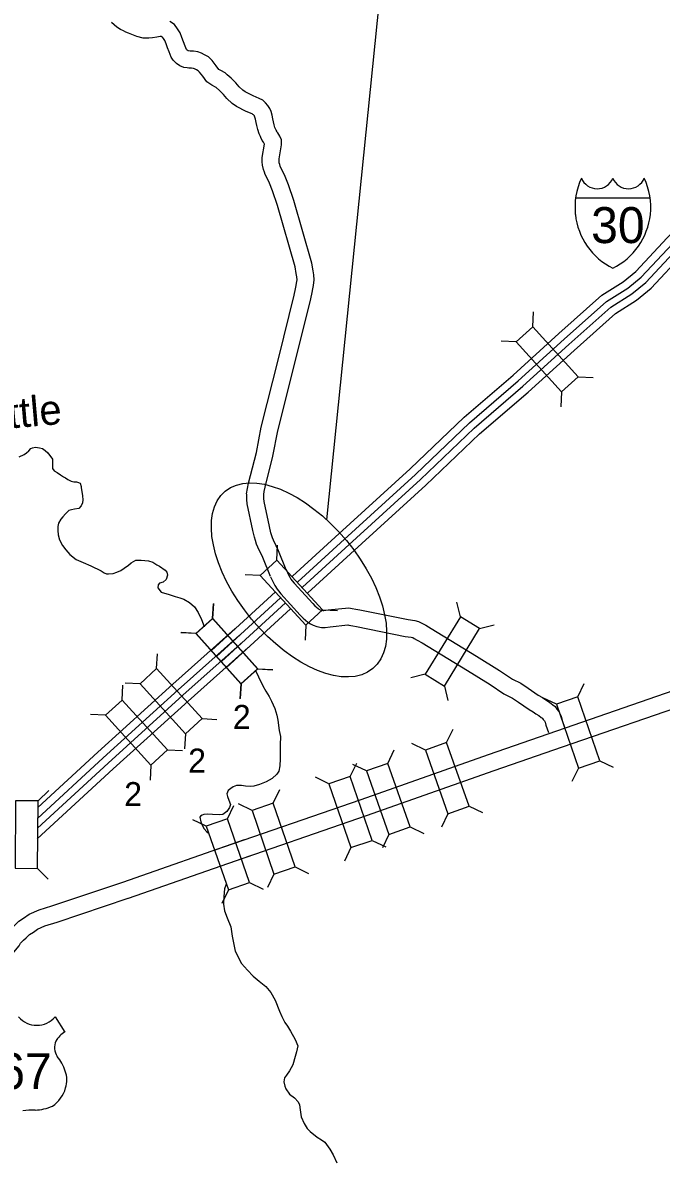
# Model space of a CAD drawing. Extents: x 8749 to 11879, y 13275 to 15339.
# Drawn here: x 9014.9 to 9239.9, y 14666 to 15065.6 of the extents above; entities that cross this region are included whole.
import ezdxf

# ---------------------------------------------------------------- set-up
doc = ezdxf.new("R2010")
doc.units = 0
for name, color, linetype in [('Level 10', 7, 'Continuous'), ('Level 15', 7, 'Continuous'), ('Level 19', 7, 'Continuous'), ('Level 2', 7, 'Continuous'), ('Level 20', 7, 'Continuous'), ('Level 22', 7, 'Continuous'), ('Level 23', 7, 'Continuous'), ('Level 9', 7, 'Continuous'), ('R_Draft', 7, 'Continuous')]:
    doc.layers.add(name, color=color, linetype=linetype)

msp = doc.modelspace()

# ---------------------------------------------------------------- linework, layer by layer
at = {"layer": 'Level 10'}
for points in [[(9093.8, 14899.41), (9093.78, 14899.73), (9094.04, 14901.56), (9094.46, 14903.38), (9097.2, 14914.21), (9098.91, 14923.18), (9105.09, 14947.68), (9110.5, 14969.7), (9110.99, 14971.93), (9111.24, 14973.07), (9111.4, 14973.93), (9111.53, 14975.1), (9111.45, 14976.12), (9111.26, 14977.27), (9110.85, 14979.62), (9104.62, 15001.21), (9102.93, 15006.38), (9101.8, 15009.08), (9101.02, 15010.9), (9100.34, 15012.19), (9100.03, 15012.93), (9099.68, 15013.94), (9099.31, 15015.39), (9099.25, 15016.66), (9099.26, 15018.16), (9100.07, 15022.89), (9099.7, 15023.51), (9099.26, 15024.13), (9098.77, 15025.17), (9098.66, 15025.51), (9098.17, 15026.52), (9097.7, 15028.06), (9097.39, 15029.37), (9097.15, 15030.48), (9096.87, 15031.7), (9096.71, 15032.41), (9096.6, 15032.65), (9096.5, 15032.82), (9096.16, 15033.16), (9095.96, 15033.35), (9095.72, 15033.47), (9093.57, 15034.38), (9090.24, 15036.07), (9088.65, 15037.17), (9086.84, 15038.92), (9085.57, 15040.34), (9084.18, 15041.71), (9083, 15042.79), (9082.84, 15042.92), (9081.57, 15043.57), (9079.76, 15044.81), (9078.29, 15046.83), (9077.19, 15048.23), (9076.7, 15048.7), (9076.14, 15049.02), (9075.4, 15049.38), (9075.09, 15049.5), (9074.39, 15049.59), (9073.45, 15049.67), (9072.79, 15049.71), (9071.71, 15049.83), (9070.29, 15050.45), (9069.06, 15051.25), (9067.88, 15052.4), (9067.17, 15053.5), (9066.45, 15055.36), (9065.95, 15056.83), (9065.41, 15058.2), (9064.97, 15059.32), (9064.47, 15060.1), (9064.14, 15060.57), (9063.93, 15060.7), (9063.76, 15060.77), (9063.67, 15060.79), (9063.34, 15060.78), (9062.17, 15060.57), (9060.58, 15060.34), (9059.36, 15060.22), (9057.38, 15060.14), (9055.14, 15060.82), (9052.16, 15061.95), (9051.26, 15062.29), (9050.36, 15062.72), (9049.33, 15063.25), (9048.09, 15064), (9046.21, 15065.72)], [(9099.81, 14899.41), (9099.8, 14899.45), (9099.95, 14900.46), (9100.29, 14901.97), (9103.06, 14912.92), (9104.77, 14921.89), (9110.91, 14946.23), (9116.34, 14968.34), (9116.85, 14970.64), (9117.13, 14971.9), (9117.34, 14973.05), (9117.56, 14975), (9117.41, 14976.86), (9117.17, 14978.28), (9116.7, 14980.97), (9110.36, 15002.98), (9108.55, 15008.47), (9107.33, 15011.42), (9106.44, 15013.49), (9105.76, 15014.76), (9105.63, 15015.08), (9105.43, 15015.66), (9105.28, 15016.26), (9105.26, 15016.79), (9105.26, 15017.65), (9106.11, 15022.63), (9106.03, 15024.38), (9105.44, 15025.61), (9104.72, 15026.8), (9104.47, 15027.15), (9104.36, 15027.39), (9104.23, 15027.77), (9103.77, 15028.73), (9103.49, 15029.63), (9103.24, 15030.69), (9103.01, 15031.77), (9102.72, 15033.04), (9102.41, 15034.38), (9101.92, 15035.42), (9101.3, 15036.49), (9100.37, 15037.43), (9099.45, 15038.32), (9098.21, 15038.93), (9096.09, 15039.83), (9093.31, 15041.24), (9092.47, 15041.82), (9091.16, 15043.08), (9089.92, 15044.47), (9088.32, 15046.06), (9086.94, 15047.31), (9086.18, 15047.95), (9084.65, 15048.74), (9084, 15049.18), (9083.07, 15050.45), (9081.66, 15052.26), (9080.31, 15053.55), (9078.95, 15054.32), (9077.82, 15054.88), (9076.57, 15055.37), (9075, 15055.56), (9073.89, 15055.65), (9073.32, 15055.69), (9073.28, 15055.69), (9073.14, 15055.75), (9072.82, 15055.96), (9072.56, 15056.21), (9072.55, 15056.24), (9072.08, 15057.42), (9071.59, 15058.88), (9071, 15060.39), (9070.33, 15062.08), (9069.44, 15063.46), (9068.37, 15064.96), (9066.74, 15066.03)], [(9102.19, 14870.6), (9099.47, 14877.22), (9097.77, 14880.85), (9097.24, 14881.99), (9096.87, 14883.22), (9096.53, 14884.46), (9095.93, 14886.79), (9093.99, 14896.19), (9093.88, 14897.7), (9093.8, 14899.41)], [(9107.75, 14872.88), (9104.97, 14879.64), (9103.21, 14883.39), (9102.86, 14884.14), (9102.64, 14884.87), (9102.33, 14885.99), (9101.78, 14888.15), (9099.95, 14897.03), (9099.87, 14898.07), (9099.81, 14899.41)], [(9107.7, 14872.99), (9108.55, 14871.14), (9108.95, 14870.35), (9109.4, 14869.64), (9109.85, 14869.08), (9110.48, 14868.17), (9117.06, 14861.05), (9117.78, 14860.28), (9118.4, 14859.77), (9118.96, 14859.27), (9119.24, 14859.09), (9119.66, 14858.88), (9120.09, 14858.72), (9120.66, 14858.62), (9121.01, 14858.63), (9122.55, 14858.79), (9129.79, 14859.56), (9130.97, 14859.28), (9132.25, 14859.07), (9133.64, 14858.8), (9150.64, 14855.4), (9153.07, 14855.06), (9154.34, 14854.68), (9155.52, 14854.17), (9156.9, 14853.39), (9158.75, 14852.3), (9174.72, 14842.55), (9182.86, 14837.51), (9187.42, 14834.44), (9190.43, 14832.95), (9192.94, 14831.27), (9196.51, 14828.81), (9197.97, 14827.97), (9199.13, 14827.12), (9200.07, 14826.51), (9201.08, 14825.79), (9201.64, 14825.39), (9202.44, 14824.74), (9203.1, 14823.83), (9203.77, 14822.97), (9204.62, 14821.32), (9204.94, 14819.84), (9205.77, 14817.52)], [(9102.24, 14870.48), (9103.15, 14868.53), (9103.74, 14867.36), (9104.52, 14866.14), (9105.03, 14865.5), (9105.8, 14864.4), (9112.66, 14856.97), (9113.66, 14855.89), (9114.51, 14855.2), (9115.32, 14854.49), (9116.28, 14853.86), (9117.25, 14853.39), (9118.46, 14852.91), (9120.21, 14852.61), (9121.41, 14852.64), (9123.19, 14852.83), (9129.41, 14853.48), (9129.79, 14853.39), (9131.18, 14853.16), (9132.48, 14852.91), (9149.63, 14849.48), (9151.79, 14849.18), (9152.28, 14849.03), (9152.85, 14848.78), (9153.91, 14848.19), (9155.66, 14847.16), (9171.58, 14837.43), (9179.61, 14832.47), (9184.4, 14829.24), (9187.42, 14827.75), (9189.57, 14826.3), (9193.3, 14823.74), (9194.68, 14822.94), (9195.72, 14822.18), (9196.69, 14821.55), (9197.6, 14820.9), (9198, 14820.62), (9198.03, 14820.59), (9198.3, 14820.22), (9198.7, 14819.71), (9198.93, 14819.27), (9199.16, 14818.19), (9200.09, 14815.59)]]:
    msp.add_lwpolyline(points, dxfattribs=at)
at = {"layer": 'Level 15'}
for points in [[(9082.3, 14774.19), (9134.08, 14792.01), (9179.01, 14807.86), (9203.08, 14816.22), (9250.19, 14832.47)], [(9084.43, 14768.58), (9136.06, 14786.34), (9180.99, 14802.2), (9205.04, 14810.55), (9252.15, 14826.8)], [(9050.15, 14762.91), (9092.98, 14777.87)], [(9052.12, 14757.24), (9094.96, 14772.2)], [(8907.81, 14602.87), (8921.05, 14621.45), (8947.08, 14657.8), (8972.67, 14693.47), (8988.96, 14716.39), (8999.9, 14731.87), (9003.89, 14737.5), (9007.02, 14741.88), (9008.71, 14743.96), (9009.42, 14745.09), (9010.95, 14746.66), (9011.98, 14747.67), (9013.58, 14749.11), (9015.15, 14750.23), (9017.12, 14751.64), (9020.65, 14753.18), (9025.2, 14754.54), (9050.18, 14762.92)], [(8915.18, 14602.87), (8925.93, 14617.96), (8951.96, 14654.31), (8977.56, 14689.98), (8993.86, 14712.92), (9004.8, 14728.41), (9008.78, 14734.02), (9011.79, 14738.24), (9013.59, 14740.45), (9014.16, 14741.36), (9015.2, 14742.43), (9016.09, 14743.3), (9017.33, 14744.42), (9018.64, 14745.34), (9020.11, 14746.4), (9022.71, 14747.54), (9027.01, 14748.81), (9052.09, 14757.23)]]:
    msp.add_lwpolyline(points, dxfattribs=at)
at = {"layer": 'Level 19'}
for points in [[(9109.92, 14870.66), (9124.94, 14884.43), (9151.41, 14908.53), (9170.43, 14926.73), (9187.67, 14941.52), (9203.82, 14956.17), (9218.94, 14969.62), (9226.41, 14974.36), (9230.86, 14977.96), (9241.9, 14989.81), (9245.61, 14993.6)], [(9111.83, 14868.69), (9126.79, 14882.4), (9153.28, 14906.52), (9172.28, 14924.69), (9189.49, 14939.46), (9205.66, 14954.13), (9220.6, 14967.41), (9228.02, 14972.12), (9232.74, 14975.94), (9243.89, 14987.91), (9247.58, 14991.68)], [(9113.46, 14866.79), (9128.48, 14880.55), (9154.99, 14904.7), (9173.96, 14922.84), (9191.14, 14937.58), (9207.33, 14952.27), (9222.11, 14965.41), (9229.48, 14970.09), (9234.45, 14974.11), (9245.7, 14986.18), (9249.37, 14989.93)], [(9115.34, 14864.79), (9130.33, 14878.52), (9156.86, 14902.69), (9175.8, 14920.8), (9192.96, 14935.52), (9209.17, 14950.22), (9223.77, 14963.21), (9231.09, 14967.85), (9236.33, 14972.09), (9247.69, 14984.28), (9251.33, 14988.01)], [(9081.38, 14844.52), (9103.94, 14865.19)], [(9083.14, 14842.4), (9105.71, 14863.08)], [(9084.89, 14840.6), (9107.42, 14861.26)], [(9086.55, 14838.4), (9109.22, 14859.18)], [(9020.2, 14789.18), (9041.41, 14808.68), (9067.8, 14832.65), (9089.68, 14852.19)], [(9020.04, 14785.3), (9043.26, 14806.65), (9069.64, 14830.6), (9091.24, 14849.9)], [(9020.08, 14781.94), (9044.95, 14804.81), (9071.32, 14828.75), (9092.5, 14847.67)], [(9020.01, 14778.14), (9046.81, 14802.78), (9073.16, 14826.7), (9094.26, 14845.56)]]:
    msp.add_lwpolyline(points, dxfattribs=at)
at = {"layer": 'Level 2'}
for points in [[(9013.68, 14912.68), (9015.4, 14913.49), (9016.25, 14914.11), (9016.99, 14914.87), (9017.79, 14915.64), (9018.35, 14915.92), (9019.39, 14916.06), (9020.82, 14915.92), (9021.84, 14915.59), (9022.83, 14914.91), (9023.79, 14914.13), (9025.43, 14911.91), (9025.44, 14911.13), (9025.42, 14910.11), (9025.4, 14909.31), (9025.36, 14908.65), (9025.94, 14907.81), (9027.05, 14907.25), (9028.21, 14906.34), (9029.31, 14905.66), (9029.95, 14905.28), (9030.79, 14904.7), (9031.99, 14904.12), (9032.89, 14903.85), (9033.89, 14903.93), (9034.55, 14903.71), (9035.09, 14903.39), (9035.45, 14902.25), (9035.54, 14901.85), (9035.66, 14900.53), (9035.98, 14898.95), (9036.09, 14897.55), (9035.91, 14896.47), (9035.45, 14895.45), (9034.64, 14894.53), (9033.16, 14894.24), (9032.08, 14894.04), (9031.14, 14893.82), (9029.97, 14892.69), (9029.05, 14891.61), (9028.31, 14890.79), (9027.54, 14889.3), (9027.28, 14888.22), (9027.28, 14886.74), (9027.35, 14885.28), (9027.89, 14883.46), (9028.96, 14881.44), (9030.04, 14879.98), (9031.51, 14878.27), (9033.73, 14876.53), (9036.17, 14875.44), (9038.91, 14874.32), (9042.47, 14872.61), (9043.6, 14871.83), (9044.38, 14871.49), (9045.14, 14871.46), (9046.75, 14871.6), (9048.03, 14872.06), (9049.41, 14872.73), (9050.63, 14873.49), (9052.12, 14874.58), (9053.12, 14875.38), (9054.74, 14876.27), (9056.61, 14876.27), (9059.25, 14876.06), (9060.69, 14875.62), (9062.16, 14874.62), (9063.04, 14874.15), (9065.02, 14872.79), (9065.64, 14872.09), (9065.92, 14871.01), (9065.39, 14869.55), (9064.35, 14868.6), (9063.11, 14868.2), (9062.6, 14867.68), (9062.5, 14866.56), (9063.62, 14865.08), (9066.46, 14864.21), (9068.62, 14863.53), (9070.3, 14863), (9071.64, 14862.52), (9073.63, 14861.4), (9075.41, 14859.93), (9076.73, 14857.91), (9077.92, 14855.41), (9078.48, 14853.89), (9078.79, 14852.87)], [(9013.68, 14912.68), (9015.4, 14913.49), (9016.25, 14914.11), (9016.99, 14914.87), (9017.79, 14915.64), (9018.35, 14915.92), (9019.39, 14916.06), (9020.82, 14915.92), (9021.84, 14915.59), (9022.83, 14914.91), (9023.79, 14914.13), (9025.43, 14911.91), (9025.44, 14911.13), (9025.42, 14910.11), (9025.4, 14909.31), (9025.36, 14908.65), (9025.94, 14907.81), (9027.05, 14907.25), (9028.21, 14906.34), (9029.31, 14905.66), (9029.95, 14905.28), (9030.79, 14904.7), (9031.99, 14904.12), (9032.89, 14903.85), (9033.89, 14903.93), (9034.55, 14903.71), (9035.09, 14903.39), (9035.45, 14902.25), (9035.54, 14901.85), (9035.66, 14900.53), (9035.98, 14898.95), (9036.09, 14897.55), (9035.91, 14896.47), (9035.45, 14895.45), (9034.64, 14894.53), (9033.16, 14894.24), (9032.08, 14894.04), (9031.14, 14893.82), (9029.97, 14892.69), (9029.05, 14891.61), (9028.31, 14890.79), (9027.54, 14889.3), (9027.28, 14888.22), (9027.28, 14886.74), (9027.35, 14885.28), (9027.89, 14883.46), (9028.96, 14881.44), (9030.04, 14879.98), (9031.51, 14878.27), (9033.73, 14876.53), (9036.17, 14875.44), (9038.91, 14874.32), (9042.47, 14872.61), (9043.6, 14871.83), (9044.38, 14871.49), (9045.14, 14871.46), (9046.75, 14871.6), (9048.03, 14872.06), (9049.41, 14872.73), (9050.63, 14873.49), (9052.12, 14874.58), (9053.12, 14875.38), (9054.74, 14876.27), (9056.61, 14876.27), (9059.25, 14876.06), (9060.69, 14875.62), (9062.16, 14874.62), (9063.04, 14874.15), (9065.02, 14872.79), (9065.64, 14872.09), (9065.92, 14871.01), (9065.39, 14869.55), (9064.35, 14868.6), (9063.11, 14868.2), (9062.6, 14867.68), (9062.5, 14866.56), (9063.62, 14865.08), (9066.46, 14864.21), (9068.62, 14863.53), (9070.3, 14863), (9071.64, 14862.52), (9073.63, 14861.4), (9075.41, 14859.93), (9076.73, 14857.91), (9077.92, 14855.41), (9078.48, 14853.89), (9078.79, 14852.87)], [(9096.89, 14837.51), (9097.94, 14835.21), (9099.45, 14832.05), (9100.58, 14830.19), (9101.7, 14828.35), (9102.59, 14826.64), (9103.77, 14824.06), (9104.46, 14821.76), (9104.76, 14820), (9105.25, 14816.36), (9105.68, 14814.2), (9105.55, 14811.23), (9105.54, 14808.45), (9105.64, 14806.33), (9105.53, 14803.91), (9105.12, 14802.03), (9104.44, 14800.94), (9102.74, 14799.36), (9100.61, 14798.23), (9098.35, 14797.3), (9096.3, 14796.74), (9095.02, 14796.56), (9093.36, 14796.73), (9091.92, 14796.91), (9090.18, 14796.96), (9088.98, 14796.48), (9088.18, 14795.92), (9087.27, 14795.19), (9086.77, 14794.03), (9086.99, 14793.03), (9087.54, 14791.73), (9088.06, 14790.31), (9087.74, 14789.15), (9086.81, 14787.77), (9085.39, 14786.72), (9084.11, 14786.64), (9081.72, 14786.71), (9079.88, 14786.85), (9078.68, 14786.73), (9078.1, 14786.48), (9077.48, 14786.12), (9077.28, 14785.76), (9077.59, 14784.16), (9078.21, 14782.74), (9078.81, 14781.64), (9079.79, 14780.64), (9080.21, 14780.33)], [(9096.89, 14837.51), (9097.94, 14835.21), (9099.45, 14832.05), (9100.58, 14830.19), (9101.7, 14828.35), (9102.59, 14826.64), (9103.77, 14824.06), (9104.46, 14821.76), (9104.76, 14820), (9105.25, 14816.36), (9105.68, 14814.2), (9105.55, 14811.23), (9105.54, 14808.45), (9105.64, 14806.33), (9105.53, 14803.91), (9105.12, 14802.03), (9104.44, 14800.94), (9102.74, 14799.36), (9100.61, 14798.23), (9098.35, 14797.3), (9096.3, 14796.74), (9095.02, 14796.56), (9093.36, 14796.73), (9091.92, 14796.91), (9090.18, 14796.96), (9088.98, 14796.48), (9088.18, 14795.92), (9087.27, 14795.19), (9086.77, 14794.03), (9086.99, 14793.03), (9087.54, 14791.73), (9088.06, 14790.31), (9087.74, 14789.15), (9086.81, 14787.77), (9085.39, 14786.72), (9084.11, 14786.64), (9081.72, 14786.71), (9079.88, 14786.85), (9078.68, 14786.73), (9078.1, 14786.48), (9077.48, 14786.12), (9077.28, 14785.76), (9077.59, 14784.16), (9078.21, 14782.74), (9078.81, 14781.64), (9079.79, 14780.64), (9080.21, 14780.33)], [(9085.95, 14760.53), (9085.78, 14757.84), (9085.64, 14755.19), (9086.02, 14752.85), (9086.91, 14750.39), (9088.21, 14747.16), (9088.72, 14743.83), (9089.26, 14740.93), (9089.73, 14738.55), (9091.95, 14734.28), (9094.04, 14731.95), (9096.06, 14729.76), (9098.24, 14727.98), (9100.57, 14726.11), (9102.35, 14724.05), (9103.84, 14721.36), (9105.3, 14717.43), (9106.21, 14715.53), (9107.27, 14713.51), (9108.15, 14712.2), (9109.29, 14710.46), (9110.88, 14707.49), (9111.76, 14705.25), (9111.3, 14703.13), (9110.85, 14701.51), (9110.09, 14698.52), (9108.83, 14696.42), (9107.88, 14694.94), (9107.12, 14694.02), (9106.88, 14692.62), (9107.26, 14691.06), (9107.54, 14690.07), (9108.93, 14688.19), (9110.67, 14686.93), (9111.99, 14685.56), (9112.45, 14684.5), (9112.64, 14682.74), (9112.96, 14680.19), (9114.06, 14677.93), (9115.09, 14676.11), (9116.11, 14675.06), (9118.61, 14673.06), (9120.11, 14672.13), (9121.36, 14671.31), (9123.1, 14668.84), (9124.26, 14666.88), (9125.57, 14664.01)], [(9085.95, 14760.53), (9085.78, 14757.84), (9085.64, 14755.19), (9086.02, 14752.85), (9086.91, 14750.39), (9088.21, 14747.16), (9088.72, 14743.83), (9089.26, 14740.93), (9089.73, 14738.55), (9091.95, 14734.28), (9094.04, 14731.95), (9096.06, 14729.76), (9098.24, 14727.98), (9100.57, 14726.11), (9102.35, 14724.05), (9103.84, 14721.36), (9105.3, 14717.43), (9106.21, 14715.53), (9107.27, 14713.51), (9108.15, 14712.2), (9109.29, 14710.46), (9110.88, 14707.49), (9111.76, 14705.25), (9111.3, 14703.13), (9110.85, 14701.51), (9110.09, 14698.52), (9108.83, 14696.42), (9107.88, 14694.94), (9107.12, 14694.02), (9106.88, 14692.62), (9107.26, 14691.06), (9107.54, 14690.07), (9108.93, 14688.19), (9110.67, 14686.93), (9111.99, 14685.56), (9112.45, 14684.5), (9112.64, 14682.74), (9112.96, 14680.19), (9114.06, 14677.93), (9115.09, 14676.11), (9116.11, 14675.06), (9118.61, 14673.06), (9120.11, 14672.13), (9121.36, 14671.31), (9123.1, 14668.84), (9124.26, 14666.88), (9125.57, 14664.01)], [(9086.57, 14762.15), (9085.95, 14760.53)], [(9086.57, 14762.15), (9085.95, 14760.53)]]:
    msp.add_lwpolyline(points, dxfattribs=at)
at = {"layer": 'Level 20'}
for p, q in [((9194.64, 14958.49), (9194.9, 14963.76)), ((9188.78, 14953.17), (9183.5, 14953.42)), ((9210.61, 14940.89), (9215.88, 14940.63)), ((9204.74, 14935.57), (9204.48, 14930.29)), ((9104.41, 14876.31), (9104.64, 14881.59)), ((9098.58, 14870.96), (9093.3, 14871.19)), ((9081.79, 14855.71), (9082.09, 14860.99)), ((9081.9, 14855.81), (9082.19, 14861.08)), ((9169.08, 14856.39), (9167.84, 14861.53)), ((9120.47, 14858.79), (9125.74, 14858.56)), ((9114.63, 14853.44), (9114.4, 14848.17)), ((9175.84, 14852.27), (9180.97, 14853.51)), ((9075.89, 14850.44), (9070.62, 14850.73)), ((9075.99, 14850.53), (9070.72, 14850.83)), ((9062.08, 14838.1), (9062.34, 14843.37)), ((9097.62, 14838), (9102.9, 14837.7)), ((9097.73, 14838.09), (9103, 14837.79)), ((9156.7, 14836.11), (9151.57, 14834.87)), ((9049.93, 14827.06), (9050.18, 14832.33)), ((9056.22, 14832.77), (9050.95, 14833.03)), ((9091.72, 14832.72), (9091.42, 14827.45)), ((9091.82, 14832.81), (9091.53, 14827.54)), ((9163.46, 14831.99), (9164.7, 14826.86)), ((9210.42, 14828.14), (9212.73, 14832.89)), ((9202.93, 14825.56), (9198.18, 14827.87)), ((9044.06, 14821.74), (9038.79, 14821.99)), ((9078.06, 14820.51), (9083.33, 14820.25)), ((9072.19, 14815.18), (9071.94, 14809.91)), ((9164.23, 14812.06), (9166.51, 14816.83)), ((9156.76, 14809.43), (9152, 14811.71)), ((9065.9, 14809.47), (9071.17, 14809.22)), ((9143.48, 14804.74), (9145.76, 14809.51)), ((9060.04, 14804.15), (9059.78, 14798.87)), ((9130.28, 14800.09), (9132.6, 14804.84)), ((9136.01, 14802.11), (9131.25, 14804.39)), ((9210.68, 14803.1), (9208.37, 14798.35)), ((9218.16, 14805.68), (9222.91, 14803.37)), ((9122.79, 14797.52), (9118.05, 14799.83)), ((9020.31, 14791.51), (9024.07, 14795.22)), ((9103.16, 14790.76), (9105.47, 14795.51)), ((9087, 14785.19), (9089.3, 14789.94)), ((9087.01, 14785.19), (9089.3, 14789.94)), ((9095.67, 14788.18), (9090.92, 14790.5)), ((9164.67, 14787.02), (9162.39, 14782.26)), ((9172.14, 14789.66), (9176.9, 14787.38)), ((9079.53, 14782.58), (9074.77, 14784.87)), ((9079.53, 14782.58), (9074.77, 14784.87)), ((9143.92, 14779.7), (9141.64, 14774.94)), ((9151.39, 14782.34), (9156.15, 14780.06)), ((9130.52, 14775.05), (9128.21, 14770.3)), ((9138.01, 14777.63), (9142.76, 14775.31)), ((9020.14, 14767.76), (9023.85, 14764)), ((9110.89, 14768.29), (9115.63, 14765.98)), ((9103.4, 14765.72), (9101.08, 14760.97)), ((9087.36, 14760.15), (9085.07, 14755.39)), ((9087.36, 14760.14), (9085.07, 14755.39)), ((9094.84, 14762.76), (9099.6, 14760.46)), ((9094.84, 14762.76), (9099.59, 14760.46))]:
    msp.add_line(p, q, dxfattribs=at)
for points in [[(9188.78, 14953.17), (9204.74, 14935.57), (9210.61, 14940.89), (9194.64, 14958.49)], [(9098.58, 14870.96), (9114.63, 14853.44), (9120.47, 14858.79), (9104.41, 14876.31)], [(9075.89, 14850.44), (9091.72, 14832.72), (9097.62, 14838), (9081.79, 14855.71)], [(9097.73, 14838.09), (9081.9, 14855.81), (9075.99, 14850.53), (9091.82, 14832.81)], [(9169.08, 14856.39), (9156.7, 14836.11), (9163.46, 14831.99), (9175.84, 14852.27)], [(9056.22, 14832.77), (9072.19, 14815.18), (9078.06, 14820.51), (9062.08, 14838.1)], [(9065.9, 14809.47), (9049.93, 14827.06), (9044.06, 14821.74), (9060.04, 14804.15)], [(9218.16, 14805.68), (9210.42, 14828.14), (9202.93, 14825.56), (9210.68, 14803.1)], [(9156.76, 14809.43), (9164.67, 14787.02), (9172.14, 14789.66), (9164.23, 14812.06)], [(9151.39, 14782.34), (9143.48, 14804.74), (9136.01, 14802.11), (9143.92, 14779.7)], [(9122.79, 14797.52), (9130.52, 14775.05), (9138.01, 14777.63), (9130.28, 14800.09)], [(9020.14, 14767.76), (9020.31, 14791.51), (9012.39, 14791.57), (9012.22, 14767.81)], [(9095.67, 14788.18), (9103.4, 14765.72), (9110.89, 14768.29), (9103.16, 14790.76)], [(9079.53, 14782.58), (9087.36, 14760.15), (9094.84, 14762.76), (9087.01, 14785.19)], [(9079.53, 14782.58), (9087.36, 14760.14), (9094.84, 14762.76), (9087, 14785.19)]]:
    msp.add_lwpolyline(points, close=True, dxfattribs=at)
at = {"layer": 'Level 22'}
msp.add_line((9026.29, 14715.47), (9029.75, 14710.11), dxfattribs=at)
for centre, radius, start, end in [((9019.84, 14720.89), 8.42, 220.3299, 319.925), ((9034.27, 14702.34), 8.99, 120.0117, 149.2191), ((9032.29, 14704.71), 6.17, 158.7892, 211.1895), ((9016.17, 14692.08), 14.38, 17.3087, 41.0435), ((9020.92, 14693.26), 9.5, 342.6181, 19.0424), ((9019.37, 14693.28), 11, 302.8688, 344.8926), ((9019.17, 14696.75), 14.12, 270.4221, 295.9229), ((9018.84, 14656.76), 25.87, 89.0461, 98.8058)]:
    msp.add_arc(centre, radius, start, end, dxfattribs=at)
at = {"layer": 'Level 23'}
msp.add_line((9209.68, 15003.98), (9235.9, 15003.98), dxfattribs=at)
for centre, radius, start, end in [((9234.05, 15000.56), 24.6, 155.2204, 185.7928), ((9217.26, 15013.13), 5.99, 202.1459, 337.3414), ((9228.32, 15013.13), 5.99, 202.6586, 337.8541), ((9211.54, 15000.56), 24.6, 354.2072, 24.7796), ((9233.6, 15000.77), 24.17, 186.3923, 243.4571), ((9211.99, 15000.77), 24.17, 296.5429, 353.6077)]:
    msp.add_arc(centre, radius, start, end, dxfattribs=at)
at = {"layer": 'R_Draft'}
msp.add_line((9122.04, 14890.48), (9162.72, 15292.43), dxfattribs=at)
msp.add_ellipse((9112.23, 14869.37), major_axis=(25.97, -31.26), ratio=0.533954, dxfattribs=at)

# ---------------------------------------------------------------- texts
at = {"layer": 'Level 20'}
for p in [(9088.92, 14816.88), (9073.18, 14801.49), (9050.64, 14789.69)]:
    msp.add_text('2', height=8.45, dxfattribs=at).set_placement(p)
at = {"layer": 'Level 22'}
msp.add_text('67', height=12.672, dxfattribs=at).set_placement((9006.25, 14689.99))
at = {"layer": 'Level 23'}
msp.add_text('30', height=12.672, dxfattribs=at).set_placement((9215.15, 14988))
at = {"layer": 'Level 9'}
msp.add_text('Little', height=10.56, rotation=5, dxfattribs=at).set_placement((8999.27, 14921.73))

doc.saveas('drawing.dxf')
